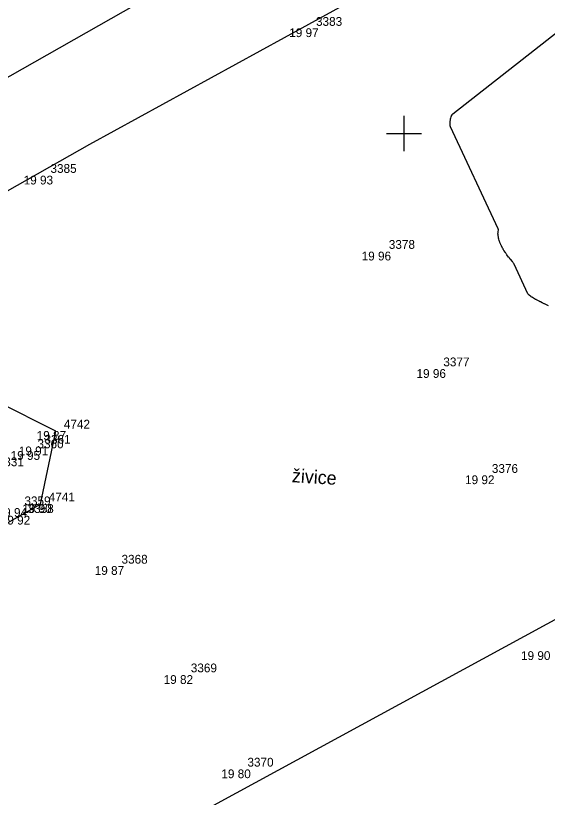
# Model space of a CAD drawing. Extents: x -702257 to -701487, y -1009871 to -1008841.
# Drawn here: x -702086.04 to -702070.92, y -1009693.87 to -1009671.65 of the extents above; entities that cross this region are included whole.
import ezdxf

# ---------------------------------------------------------------- set-up
doc = ezdxf.new("R2010")
doc.units = 0
for name, color, linetype in [('Ex_Major Contours', 7, 'Continuous'), ('Z_body', 7, 'Continuous'), ('Z_body_cisla', 7, 'Continuous'), ('Z_body_vysky_redukovane', 7, 'Continuous'), ('Z_hektometricka_sit', 7, 'Continuous'), ('Z_katastr_hranice', 7, 'Continuous'), ('Z_komunikace', 7, 'Continuous'), ('Z_popisy', 7, 'Continuous'), ('Z_vdz_prechod', 7, 'Continuous')]:
    doc.layers.add(name, color=color, linetype=linetype)

# ---------------------------------------------------------------- blocks, each defined once
blk = doc.blocks.new('POINT_DISPLAY')
blk.add_line((0, 0), (0, 0))

msp = doc.modelspace()

# ---------------------------------------------------------------- linework, layer by layer
at = {"layer": 'Ex_Major Contours'}
msp.add_lwpolyline([(-702070.887, -1009679.897), (-702070.988, -1009679.853), (-702071.003, -1009679.847), (-702071.017, -1009679.84), (-702071.053, -1009679.823), (-702071.067, -1009679.816), (-702071.074, -1009679.813), (-702071.118, -1009679.791), (-702071.128, -1009679.786), (-702071.138, -1009679.781), (-702071.147, -1009679.776), (-702071.157, -1009679.771), (-702071.23, -1009679.732), (-702071.244, -1009679.724), (-702071.258, -1009679.716), (-702071.272, -1009679.708), (-702071.286, -1009679.7), (-702071.342, -1009679.665), (-702071.355, -1009679.658), (-702071.367, -1009679.65), (-702071.379, -1009679.642), (-702071.391, -1009679.633), (-702071.44, -1009679.6), (-702071.451, -1009679.591), (-702071.461, -1009679.581), (-702071.469, -1009679.569), (-702071.476, -1009679.557), (-702071.869, -1009678.715), (-702071.879, -1009678.696), (-702071.89, -1009678.677), (-702071.902, -1009678.66), (-702071.915, -1009678.643), (-702071.973, -1009678.576), (-702071.986, -1009678.56), (-702071.999, -1009678.545), (-702072.011, -1009678.53), (-702072.023, -1009678.514), (-702072.073, -1009678.448), (-702072.084, -1009678.433), (-702072.095, -1009678.418), (-702072.105, -1009678.404), (-702072.115, -1009678.388), (-702072.157, -1009678.325), (-702072.166, -1009678.311), (-702072.174, -1009678.297), (-702072.182, -1009678.283), (-702072.19, -1009678.269), (-702072.223, -1009678.208), (-702072.23, -1009678.195), (-702072.236, -1009678.182), (-702072.243, -1009678.169), (-702072.248, -1009678.155), (-702072.273, -1009678.098), (-702072.277, -1009678.086), (-702072.282, -1009678.074), (-702072.286, -1009678.062), (-702072.29, -1009678.049), (-702072.305, -1009677.997), (-702072.309, -1009677.985), (-702072.311, -1009677.974), (-702072.313, -1009677.963), (-702072.315, -1009677.952), (-702072.323, -1009677.904), (-702072.324, -1009677.893), (-702072.325, -1009677.883), (-702072.325, -1009677.873), (-702072.326, -1009677.863), (-702072.325, -1009677.82), (-702072.325, -1009677.81), (-702072.324, -1009677.801), (-702072.323, -1009677.792), (-702072.322, -1009677.783), (-702072.315, -1009677.746), (-702072.314, -1009677.737), (-702072.314, -1009677.728), (-702072.316, -1009677.719), (-702072.319, -1009677.711), (-702073.675, -1009674.813), (-702073.68, -1009674.801), (-702073.684, -1009674.788), (-702073.686, -1009674.775), (-702073.687, -1009674.761), (-702073.688, -1009674.703), (-702073.688, -1009674.692), (-702073.687, -1009674.68), (-702073.686, -1009674.669), (-702073.685, -1009674.657), (-702073.679, -1009674.608), (-702073.677, -1009674.598), (-702073.676, -1009674.589), (-702073.673, -1009674.579), (-702073.671, -1009674.569), (-702073.658, -1009674.529), (-702073.656, -1009674.521), (-702073.652, -1009674.512), (-702073.649, -1009674.504), (-702073.645, -1009674.497), (-702073.628, -1009674.466), (-702073.624, -1009674.458), (-702073.619, -1009674.451), (-702073.613, -1009674.445), (-702073.606, -1009674.439), (-702067.212, -1009669.415)], dxfattribs=at)
at = {"layer": 'Z_hektometricka_sit'}
for p, q in [((-702075, -1009674.5), (-702075, -1009675.5)), ((-702075.5, -1009675), (-702074.5, -1009675))]:
    msp.add_line(p, q, dxfattribs=at)
at = {"layer": 'Z_katastr_hranice'}
for p, q in [((-702083.93, -1009675.3), (-702040.13, -1009651.3)), ((-702094.22, -1009681.12), (-702083.93, -1009675.3)), ((-702068.73, -1009687.75), (-702082.23, -1009695.09))]:
    msp.add_line(p, q, dxfattribs=at)
at = {"layer": 'Z_komunikace'}
for p, q in [((-702084.9, -1009683.46), (-702087.02, -1009682.4)), ((-702085.33, -1009685.54), (-702084.9, -1009683.46)), ((-702085.92, -1009685.87), (-702085.33, -1009685.54)), ((-702088.49, -1009687.32), (-702085.92, -1009685.87))]:
    msp.add_line(p, q, dxfattribs=at)
at = {"layer": 'Z_vdz_prechod'}
msp.add_line((-702082.63, -1009671.34), (-702090.08, -1009675.56), dxfattribs=at)

# ---------------------------------------------------------------- block references
at = {"layer": 'Z_body'}
for p in [(-702077.72, -1009672.01), (-702085.27, -1009676.2), (-702075.66, -1009678.36), (-702074.1, -1009681.7), (-702084.9, -1009683.46), (-702085.45, -1009683.9), (-702085.64, -1009684.03), (-702072.72, -1009684.72), (-702086.01, -1009685.65), (-702085.33, -1009685.54), (-702085.92, -1009685.87), (-702083.25, -1009687.3), (-702071.15, -1009689.72), (-702081.29, -1009690.4), (-702079.67, -1009693.08)]:
    msp.add_blockref('POINT_DISPLAY', p, dxfattribs=at)

# ---------------------------------------------------------------- texts
at = {"layer": 'Z_body_cisla'}
for s, p in [('3383', (-702077.5, -1009671.94)), ('3385', (-702085.05, -1009676.12)), ('3378', (-702075.43, -1009678.28)), ('3377', (-702073.88, -1009681.62)), ('4742', (-702084.67, -1009683.39)), ('3360', (-702085.42, -1009683.95)), ('3361', (-702085.22, -1009683.82)), ('3331', (-702086.55, -1009684.46)), ('3376', (-702072.5, -1009684.65)), ('4741', (-702085.1, -1009685.46)), ('3359', (-702085.79, -1009685.57)), ('3358', (-702085.7, -1009685.79)), ('3368', (-702083.03, -1009687.23)), ('3369', (-702081.06, -1009690.32)), ('3370', (-702079.45, -1009693))]:
    msp.add_text(s, height=0.25, dxfattribs=at).set_placement(p)
at = {"layer": 'Z_body_vysky_redukovane'}
for s, p in [('19 97', (-702078.262, -1009672.26)), ('19 93', (-702085.812, -1009676.45)), ('19 96', (-702076.202, -1009678.61)), ('19 96', (-702074.642, -1009681.95)), ('19 87', (-702085.442, -1009683.71)), ('19 91', (-702085.95, -1009684.15)), ('19 95', (-702086.182, -1009684.28)), ('19 92', (-702073.262, -1009684.97)), ('19 94', (-702086.552, -1009685.9)), ('19 90', (-702085.851, -1009685.79)), ('19 92', (-702086.462, -1009686.12)), ('19 87', (-702083.792, -1009687.55)), ('19 90', (-702071.671, -1009689.97)), ('19 82', (-702081.832, -1009690.65)), ('19 80', (-702080.191, -1009693.33))]:
    msp.add_text(s, height=0.25, dxfattribs=at).set_placement(p)
at = {"layer": 'Z_popisy'}
msp.add_text('živice', height=0.38, rotation=356.4, dxfattribs=at).set_placement((-702078.193, -1009684.913))

doc.saveas('drawing.dxf')
